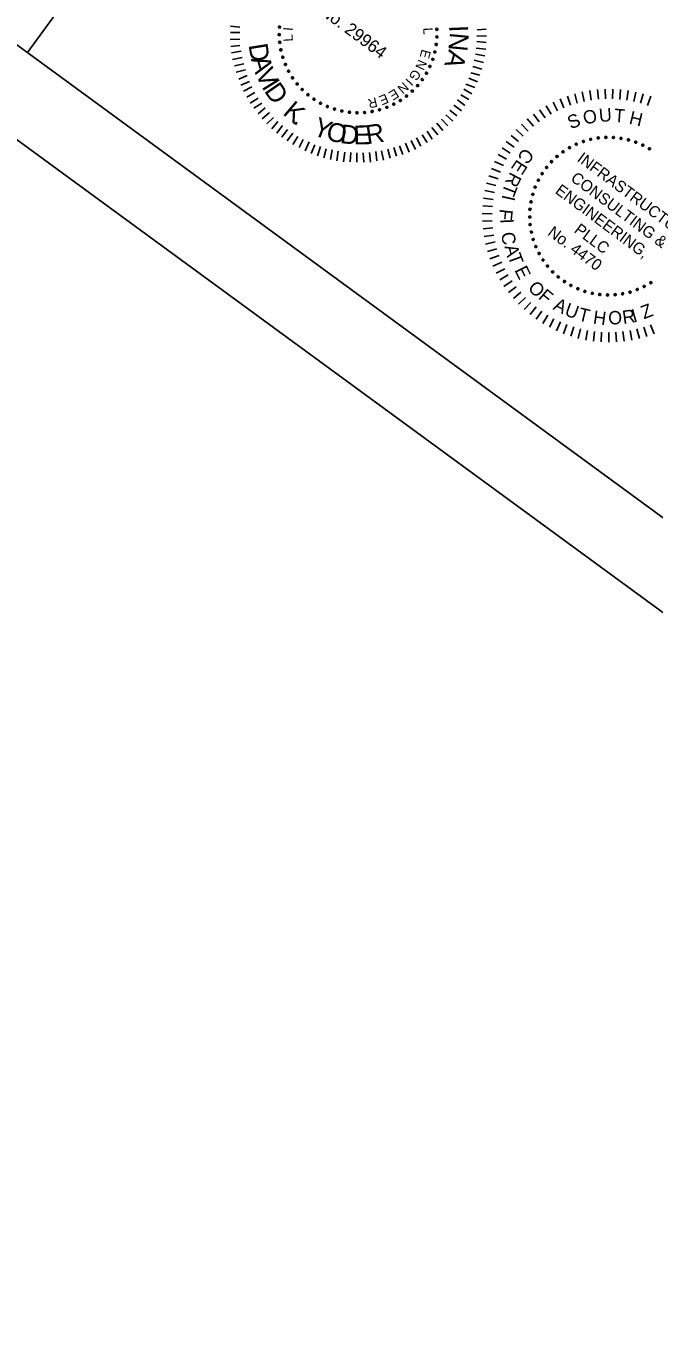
# Model space of a CAD drawing. Extents: x 1970654 to 1970899, y 796145 to 796378.
# Drawn here: x 1970805.45 to 1970821.89, y 796145.21 to 796179.11 of the extents above; entities that cross this region are included whole.
import ezdxf

# ---------------------------------------------------------------- set-up
doc = ezdxf.new("R2010")
doc.units = 0
for name, color, linetype in [('BR_BORDER LINES', 7, 'Continuous'), ('BR_TEXT', 7, 'Continuous'), ('Level 31', 7, 'Continuous')]:
    doc.layers.add(name, color=color, linetype=linetype)

msp = doc.modelspace()

# ---------------------------------------------------------------- linework, layer by layer
at = {"layer": 'BR_BORDER LINES'}
for p, q in [((1970738.359, 796227.562), (1970847.014, 796148.01)), ((1970805.492, 796178.411), (1970811.99, 796187.287))]:
    msp.add_line(p, q, dxfattribs=at)
at = {"layer": 'BR_TEXT'}
for p, q in [((1970811.052, 796179.077), (1970810.803, 796179.104)), ((1970817.254, 796179.007), (1970817.495, 796179.021)), ((1970811.054, 796178.763), (1970810.8, 796178.756)), ((1970811.051, 796178.932), (1970810.803, 796178.933)), ((1970817.251, 796178.843), (1970817.502, 796178.852)), ((1970817.253, 796178.696), (1970817.498, 796178.675)), ((1970811.054, 796178.596), (1970810.815, 796178.569)), ((1970811.086, 796178.444), (1970810.834, 796178.405)), ((1970817.212, 796178.371), (1970817.462, 796178.321)), ((1970817.236, 796178.524), (1970817.483, 796178.499)), ((1970811.107, 796178.278), (1970810.862, 796178.23)), ((1970811.151, 796178.118), (1970810.908, 796178.062)), ((1970817.144, 796178.044), (1970817.377, 796177.978)), ((1970817.181, 796178.209), (1970817.423, 796178.154)), ((1970811.197, 796177.955), (1970810.955, 796177.895)), ((1970811.244, 796177.812), (1970811.02, 796177.718)), ((1970811.304, 796177.657), (1970811.076, 796177.557)), ((1970817.039, 796177.742), (1970817.266, 796177.645)), ((1970817.092, 796177.882), (1970817.33, 796177.816)), ((1970811.367, 796177.511), (1970811.148, 796177.396)), ((1970811.444, 796177.368), (1970811.234, 796177.247)), ((1970816.907, 796177.45), (1970817.116, 796177.334)), ((1970816.966, 796177.587), (1970817.196, 796177.493)), ((1970819.809, 796177.331), (1970819.878, 796177.086)), ((1970820.005, 796177.38), (1970820.059, 796177.131)), ((1970820.204, 796177.416), (1970820.243, 796177.164)), ((1970820.404, 796177.441), (1970820.428, 796177.187)), ((1970820.606, 796177.453), (1970820.614, 796177.198)), ((1970820.808, 796177.452), (1970820.8, 796177.198)), ((1970821.009, 796177.44), (1970820.986, 796177.186)), ((1970821.21, 796177.415), (1970821.171, 796177.163)), ((1970821.408, 796177.378), (1970821.354, 796177.129)), ((1970821.604, 796177.329), (1970821.535, 796177.084)), ((1970811.527, 796177.221), (1970811.323, 796177.09)), ((1970811.625, 796177.088), (1970811.414, 796176.954)), ((1970816.652, 796177.033), (1970816.847, 796176.888)), ((1970816.742, 796177.171), (1970816.935, 796177.028)), ((1970816.831, 796177.302), (1970817.043, 796177.178)), ((1970819.066, 796177.02), (1970819.192, 796176.799)), ((1970819.244, 796177.115), (1970819.357, 796176.886)), ((1970819.428, 796177.198), (1970819.526, 796176.964)), ((1970819.617, 796177.27), (1970819.7, 796177.03)), ((1970821.797, 796177.268), (1970821.713, 796177.028)), ((1970811.712, 796176.963), (1970811.526, 796176.806)), ((1970811.828, 796176.843), (1970811.633, 796176.68)), ((1970811.928, 796176.713), (1970811.758, 796176.548)), ((1970816.323, 796176.666), (1970816.49, 796176.494)), ((1970816.443, 796176.782), (1970816.62, 796176.611)), ((1970816.541, 796176.902), (1970816.73, 796176.752)), ((1970818.569, 796176.674), (1970818.734, 796176.48)), ((1970818.728, 796176.8), (1970818.88, 796176.596)), ((1970818.893, 796176.915), (1970819.033, 796176.702)), ((1970812.044, 796176.605), (1970811.883, 796176.417)), ((1970812.165, 796176.502), (1970812.017, 796176.304)), ((1970812.293, 796176.393), (1970812.148, 796176.198)), ((1970812.434, 796176.301), (1970812.292, 796176.099)), ((1970815.952, 796176.352), (1970816.085, 796176.146)), ((1970816.073, 796176.445), (1970816.231, 796176.255)), ((1970816.201, 796176.56), (1970816.361, 796176.372)), ((1970818.277, 796176.396), (1970818.464, 796176.223)), ((1970818.419, 796176.539), (1970818.595, 796176.355)), ((1970812.57, 796176.213), (1970812.436, 796176.005)), ((1970812.704, 796176.134), (1970812.598, 796175.923)), ((1970812.86, 796176.074), (1970812.756, 796175.843)), ((1970813.008, 796175.997), (1970812.917, 796175.771)), ((1970815.223, 796175.97), (1970815.315, 796175.743)), ((1970815.382, 796176.035), (1970815.477, 796175.806)), ((1970815.528, 796176.111), (1970815.641, 796175.877)), ((1970815.672, 796176.183), (1970815.788, 796175.96)), ((1970815.816, 796176.261), (1970815.946, 796176.056)), ((1970818.021, 796176.084), (1970818.228, 796175.935)), ((1970818.144, 796176.244), (1970818.341, 796176.082)), ((1970813.156, 796175.948), (1970813.085, 796175.709)), ((1970813.311, 796175.892), (1970813.244, 796175.659)), ((1970813.468, 796175.861), (1970813.422, 796175.616)), ((1970813.624, 796175.83), (1970813.59, 796175.577)), ((1970813.793, 796175.803), (1970813.765, 796175.554)), ((1970813.953, 796175.795), (1970813.935, 796175.547)), ((1970814.112, 796175.783), (1970814.113, 796175.543)), ((1970814.278, 796175.788), (1970814.294, 796175.54)), ((1970814.441, 796175.795), (1970814.468, 796175.544)), ((1970814.604, 796175.823), (1970814.633, 796175.575)), ((1970814.756, 796175.838), (1970814.809, 796175.593)), ((1970814.924, 796175.88), (1970814.979, 796175.643)), ((1970815.081, 796175.93), (1970815.15, 796175.695)), ((1970817.805, 796175.743), (1970818.028, 796175.62)), ((1970817.908, 796175.916), (1970818.123, 796175.78)), ((1970817.632, 796175.378), (1970817.868, 796175.283)), ((1970817.713, 796175.563), (1970817.943, 796175.454)), ((1970817.504, 796174.995), (1970817.75, 796174.93)), ((1970817.562, 796175.188), (1970817.804, 796175.108)), ((1970817.424, 796174.599), (1970817.677, 796174.565)), ((1970817.458, 796174.798), (1970817.708, 796174.748)), ((1970817.403, 796174.399), (1970817.657, 796174.379)), ((1970817.393, 796174.197), (1970817.648, 796174.193)), ((1970817.396, 796173.995), (1970817.651, 796174.007)), ((1970817.411, 796173.794), (1970817.665, 796173.821)), ((1970817.439, 796173.593), (1970817.69, 796173.636)), ((1970817.478, 796173.395), (1970817.726, 796173.453)), ((1970817.53, 796173.2), (1970817.774, 796173.273)), ((1970817.593, 796173.009), (1970817.833, 796173.096)), ((1970817.668, 796172.821), (1970817.902, 796172.923)), ((1970817.755, 796172.638), (1970817.981, 796172.754)), ((1970817.852, 796172.461), (1970818.071, 796172.591)), ((1970817.96, 796172.291), (1970818.171, 796172.433)), ((1970818.078, 796172.127), (1970818.28, 796172.282)), ((1970818.206, 796171.971), (1970818.397, 796172.138)), ((1970818.343, 796171.822), (1970818.524, 796172.001)), ((1970818.489, 796171.683), (1970818.659, 796171.872)), ((1970818.643, 796171.552), (1970818.801, 796171.752)), ((1970818.804, 796171.431), (1970818.95, 796171.64)), ((1970818.973, 796171.321), (1970819.106, 796171.538)), ((1970819.149, 796171.22), (1970819.268, 796171.445)), ((1970819.33, 796171.131), (1970819.435, 796171.363)), ((1970819.516, 796171.053), (1970819.607, 796171.291)), ((1970819.707, 796170.986), (1970819.783, 796171.229)), ((1970821.695, 796170.984), (1970821.618, 796171.227)), ((1970821.886, 796171.051), (1970821.795, 796171.288)), ((1970819.901, 796170.931), (1970819.962, 796171.178)), ((1970820.098, 796170.888), (1970820.144, 796171.139)), ((1970820.298, 796170.857), (1970820.329, 796171.11)), ((1970820.499, 796170.839), (1970820.514, 796171.093)), ((1970820.701, 796170.832), (1970820.701, 796171.087)), ((1970820.902, 796170.838), (1970820.887, 796171.093)), ((1970821.104, 796170.857), (1970821.072, 796171.109)), ((1970821.303, 796170.887), (1970821.257, 796171.138)), ((1970821.501, 796170.93), (1970821.439, 796171.177))]:
    msp.add_line(p, q, dxfattribs=at)
for centre, start, end in [((1970812.088, 796179.076), 85.1636, 265.1636), ((1970812.088, 796179.076), 265.1636, 85.1636), ((1970816.202, 796179.019), 93.4713, 273.4713), ((1970816.202, 796179.019), 273.4713, 93.4713), ((1970812.08, 796178.877), 90.702, 270.702), ((1970812.092, 796178.678), 96.2405, 276.2405), ((1970812.08, 796178.877), 270.702, 90.702), ((1970812.092, 796178.678), 276.2405, 96.2405), ((1970816.204, 796178.82), 87.9328, 267.9328), ((1970816.204, 796178.82), 267.9328, 87.9328), ((1970812.123, 796178.481), 101.779, 281.779), ((1970812.123, 796178.481), 281.779, 101.779), ((1970816.151, 796178.425), 76.8559, 256.8559), ((1970816.151, 796178.425), 256.8559, 76.8559), ((1970816.187, 796178.621), 82.3943, 262.3943), ((1970816.187, 796178.621), 262.3943, 82.3943), ((1970812.173, 796178.288), 107.3174, 287.3174), ((1970812.173, 796178.288), 287.3174, 107.3174), ((1970812.241, 796178.101), 112.8559, 292.8559), ((1970812.241, 796178.101), 292.8559, 112.8559), ((1970816.023, 796178.048), 65.779, 245.779), ((1970816.023, 796178.048), 245.779, 65.779), ((1970816.096, 796178.233), 71.3174, 251.3174), ((1970816.096, 796178.233), 251.3174, 71.3174), ((1970812.327, 796177.921), 118.3943, 298.3943), ((1970812.327, 796177.921), 298.3943, 118.3943), ((1970812.429, 796177.75), 123.9328, 303.9328), ((1970812.429, 796177.75), 303.9328, 123.9328), ((1970815.824, 796177.703), 54.702, 234.702), ((1970815.824, 796177.703), 234.702, 54.702), ((1970815.932, 796177.871), 60.2405, 240.2405), ((1970815.932, 796177.871), 240.2405, 60.2405), ((1970812.548, 796177.59), 129.4713, 309.4713), ((1970812.548, 796177.59), 309.4713, 129.4713), ((1970812.682, 796177.442), 135.0097, 315.0097), ((1970812.682, 796177.442), 315.0097, 135.0097), ((1970812.829, 796177.308), 140.5482, 320.5482), ((1970812.829, 796177.308), 320.5482, 140.5482), ((1970815.563, 796177.402), 43.6251, 223.6251), ((1970815.563, 796177.402), 223.6251, 43.6251), ((1970815.701, 796177.546), 49.1636, 229.1636), ((1970815.701, 796177.546), 229.1636, 49.1636), ((1970812.989, 796177.188), 146.0866, 326.0866), ((1970812.989, 796177.188), 326.0866, 146.0866), ((1970813.159, 796177.085), 151.6251, 331.6251), ((1970813.159, 796177.085), 331.6251, 151.6251), ((1970813.339, 796176.999), 157.1636, 337.1636), ((1970813.339, 796176.999), 337.1636, 157.1636), ((1970814.894, 796176.977), 21.4713, 201.4713), ((1970814.894, 796176.977), 201.4713, 21.4713), ((1970815.076, 796177.058), 27.0097, 207.0097), ((1970815.076, 796177.058), 207.0097, 27.0097), ((1970815.25, 796177.157), 32.5482, 212.5482), ((1970815.25, 796177.157), 212.5482, 32.5482), ((1970815.412, 796177.272), 38.0866, 218.0866), ((1970815.412, 796177.272), 218.0866, 38.0866), ((1970813.526, 796176.93), 162.702, 342.702), ((1970813.526, 796176.93), 342.702, 162.702), ((1970813.719, 796176.879), 348.2405, 168.2405), ((1970813.719, 796176.879), 168.2405, 348.2405), ((1970813.916, 796176.848), 353.779, 173.779), ((1970813.916, 796176.848), 173.779, 353.779), ((1970814.114, 796176.835), 359.3174, 179.3174), ((1970814.114, 796176.835), 179.3174, 359.3174), ((1970814.314, 796176.842), 4.8559, 184.8559), ((1970814.314, 796176.842), 184.8559, 4.8559), ((1970814.511, 796176.868), 10.3943, 190.3943), ((1970814.511, 796176.868), 190.3943, 10.3943), ((1970814.705, 796176.913), 15.9328, 195.9328), ((1970814.705, 796176.913), 195.9328, 15.9328), ((1970819.851, 796176.012), 24.2405, 204.2405), ((1970819.851, 796176.012), 204.2405, 24.2405), ((1970820.037, 796176.085), 18.702, 198.702), ((1970820.037, 796176.085), 198.702, 18.702), ((1970820.229, 796176.139), 13.1636, 193.1636), ((1970820.229, 796176.139), 193.1636, 13.1636), ((1970820.425, 796176.175), 7.6251, 187.6251), ((1970820.425, 796176.175), 187.6251, 7.6251), ((1970820.623, 796176.191), 2.0866, 182.0866), ((1970820.623, 796176.191), 182.0866, 2.0866), ((1970820.823, 796176.188), 356.5482, 176.5482), ((1970820.823, 796176.188), 176.5482, 356.5482), ((1970821.021, 796176.166), 351.0097, 171.0097), ((1970821.021, 796176.166), 171.0097, 351.0097), ((1970821.216, 796176.125), 165.4713, 345.4713), ((1970821.216, 796176.125), 345.4713, 165.4713), ((1970821.406, 796176.066), 159.9328, 339.9328), ((1970821.406, 796176.066), 339.9328, 159.9328), ((1970821.589, 796175.988), 154.3943, 334.3943), ((1970821.589, 796175.988), 334.3943, 154.3943), ((1970819.348, 796175.692), 40.8559, 220.8559), ((1970819.348, 796175.692), 220.8559, 40.8559), ((1970819.505, 796175.815), 35.3174, 215.3174), ((1970819.505, 796175.815), 215.3174, 35.3174), ((1970819.673, 796175.922), 29.779, 209.779), ((1970819.673, 796175.922), 209.779, 29.779), ((1970821.765, 796175.893), 148.8559, 328.8559), ((1970821.765, 796175.893), 328.8559, 148.8559), ((1970819.073, 796175.405), 51.9328, 231.9328), ((1970819.073, 796175.405), 231.9328, 51.9328), ((1970819.203, 796175.555), 46.3943, 226.3943), ((1970819.203, 796175.555), 226.3943, 46.3943), ((1970818.858, 796175.069), 63.0097, 243.0097), ((1970818.858, 796175.069), 243.0097, 63.0097), ((1970818.957, 796175.242), 57.4713, 237.4713), ((1970818.957, 796175.242), 237.4713, 57.4713), ((1970818.712, 796174.699), 74.0866, 254.0866), ((1970818.712, 796174.699), 254.0866, 74.0866), ((1970818.776, 796174.888), 68.5482, 248.5482), ((1970818.776, 796174.888), 248.5482, 68.5482), ((1970818.639, 796174.308), 85.1636, 265.1636), ((1970818.639, 796174.308), 265.1636, 85.1636), ((1970818.666, 796174.505), 79.6251, 259.6251), ((1970818.666, 796174.505), 259.6251, 79.6251), ((1970818.632, 796174.108), 90.702, 270.702), ((1970818.643, 796173.909), 96.2405, 276.2405), ((1970818.632, 796174.108), 270.702, 90.702), ((1970818.643, 796173.909), 276.2405, 96.2405), ((1970818.674, 796173.712), 101.779, 281.779), ((1970818.674, 796173.712), 281.779, 101.779), ((1970818.724, 796173.519), 107.3174, 287.3174), ((1970818.724, 796173.519), 287.3174, 107.3174), ((1970818.792, 796173.332), 112.8559, 292.8559), ((1970818.792, 796173.332), 292.8559, 112.8559), ((1970818.878, 796173.152), 118.3943, 298.3943), ((1970818.878, 796173.152), 298.3943, 118.3943), ((1970818.981, 796172.981), 123.9328, 303.9328), ((1970818.981, 796172.981), 303.9328, 123.9328), ((1970819.099, 796172.821), 129.4713, 309.4713), ((1970819.099, 796172.821), 309.4713, 129.4713), ((1970819.233, 796172.674), 135.0097, 315.0097), ((1970819.233, 796172.674), 315.0097, 135.0097), ((1970819.38, 796172.539), 320.5482, 140.5482), ((1970819.38, 796172.539), 140.5482, 320.5482), ((1970819.54, 796172.42), 146.0866, 326.0866), ((1970819.54, 796172.42), 326.0866, 146.0866), ((1970819.71, 796172.316), 151.6251, 331.6251), ((1970819.71, 796172.316), 331.6251, 151.6251), ((1970819.89, 796172.23), 157.1636, 337.1636), ((1970819.89, 796172.23), 337.1636, 157.1636), ((1970821.446, 796172.208), 21.4713, 201.4713), ((1970821.627, 796172.29), 27.0097, 207.0097), ((1970821.627, 796172.29), 207.0097, 27.0097), ((1970821.801, 796172.388), 32.5482, 212.5482), ((1970821.801, 796172.388), 212.5482, 32.5482), ((1970820.077, 796172.161), 162.702, 342.702), ((1970820.077, 796172.161), 342.702, 162.702), ((1970820.27, 796172.111), 348.2405, 168.2405), ((1970820.27, 796172.111), 168.2405, 348.2405), ((1970820.467, 796172.079), 353.779, 173.779), ((1970820.467, 796172.079), 173.779, 353.779), ((1970820.666, 796172.067), 359.3174, 179.3174), ((1970820.666, 796172.067), 179.3174, 359.3174), ((1970820.865, 796172.074), 4.8559, 184.8559), ((1970820.865, 796172.074), 184.8559, 4.8559), ((1970821.062, 796172.1), 10.3943, 190.3943), ((1970821.062, 796172.1), 190.3943, 10.3943), ((1970821.257, 796172.145), 15.9328, 195.9328), ((1970821.257, 796172.145), 195.9328, 15.9328), ((1970821.446, 796172.208), 201.4713, 21.4713)]:
    msp.add_arc(centre, 0.028, start, end, dxfattribs=at)
at = {"layer": 'Level 31'}
msp.add_lwpolyline([(1970731.261, 796230.28), (1970847.449, 796145.214), (1970899.434, 796216.218), (1970783.245, 796301.284)], close=True, dxfattribs=at)

# ---------------------------------------------------------------- texts
at = {"layer": 'BR_TEXT'}
for s, height, rotation, p in [('No. 29964', 0.327, 323.3174, (1970813.121, 796179.439)), ('I', 0.249, 84.8917, (1970812.431, 796178.97)), ('L', 0.249, 273.2452, (1970815.846, 796179.057)), ('I', 0.496, 272.4519, (1970816.522, 796179.116)), ('L', 0.249, 93.7501, (1970812.439, 796178.706)), ('N', 0.496, 264.4942, (1970816.551, 796178.949)), ('D', 0.494, 279.1958, (1970811.277, 796178.611)), ('E', 0.249, 254.8396, (1970815.812, 796178.511)), ('A', 0.496, 253.2698, (1970816.523, 796178.509)), ('A', 0.494, 286.6283, (1970811.337, 796178.242)), ('V', 0.494, 294.3085, (1970811.448, 796177.872)), ('N', 0.249, 245.6372, (1970815.73, 796178.248)), ('I', 0.494, 301.9887, (1970811.608, 796177.52)), ('I', 0.249, 226.1989, (1970815.426, 796177.756)), ('G', 0.249, 236.09, (1970815.602, 796177.994)), ('D', 0.494, 304.5901, (1970811.673, 796177.406)), ('E', 0.249, 202.775, (1970814.87, 796177.339)), ('E', 0.249, 211.9773, (1970815.109, 796177.475)), ('N', 0.249, 221.5245, (1970815.33, 796177.655)), ('K', 0.494, 319.8885, (1970812.151, 796176.805)), ('R', 0.249, 193.5726, (1970814.613, 796177.242)), ('Y', 0.494, 338.6555, (1970812.927, 796176.273)), ('S', 0.349, 22.6989, (1970819.709, 796176.397)), ('O', 0.349, 13.6688, (1970820.073, 796176.518)), ('U', 0.349, 4.6388, (1970820.457, 796176.589)), ('T', 0.349, 355.6088, (1970820.826, 796176.597)), ('H', 0.349, 346.5788, (1970821.212, 796176.55)), ('.', 0.494, 326.9494, (1970812.422, 796176.576)), ('O', 0.494, 346.2118, (1970813.281, 796176.135)), ('D', 0.494, 353.892, (1970813.657, 796176.044)), ('E', 0.494, 1.3245, (1970814.029, 796176.004)), ('R', 0.494, 8.3853, (1970814.384, 796176.011)), ('C', 0.349, 230.8156, (1970818.506, 796175.939)), ('INFRASTRUCTURE', 0.29909, 323.3174, (1970819.852, 796175.586)), ('E', 0.349, 236.8156, (1970818.304, 796175.633)), ('R', 0.349, 242.8156, (1970818.127, 796175.305)), ('ENGINEERING,', 0.29909, 323.3174, (1970819.277, 796174.748)), ('CONSULTING &', 0.29909, 323.3174, (1970819.681, 796175.073)), ('I', 0.349, 257.5619, (1970817.921, 796174.704)), ('T', 0.349, 248.8156, (1970817.997, 796175.01)), ('F', 0.349, 263.5619, (1970817.85, 796174.329)), ('I', 0.349, 272.3174, (1970817.859, 796174.055)), ('PLLC', 0.2991, 323.3174, (1970819.773, 796173.722)), ('C', 0.349, 278.3174, (1970817.885, 796173.689)), ('No. 4470', 0.2991, 323.3174, (1970819.079, 796173.651)), ('A', 0.349, 284.3174, (1970817.969, 796173.336)), ('T', 0.349, 290.3174, (1970818.054, 796173.084)), ('E', 0.349, 296.3174, (1970818.227, 796172.72)), ('O', 0.349, 314.3174, (1970818.564, 796172.231)), ('F', 0.349, 320.3174, (1970818.838, 796171.986)), ('A', 0.349, 334.3174, (1970819.221, 796171.697)), ('U', 0.349, 340.3174, (1970819.523, 796171.542)), ('T', 0.349, 346.3174, (1970819.877, 796171.404)), ('H', 0.349, 352.3174, (1970820.276, 796171.319)), ('O', 0.349, 2.3174, (1970820.693, 796171.291)), ('R', 0.349, 8.3174, (1970821.082, 796171.304)), ('I', 0.349, 16.1245, (1970821.353, 796171.34)), ('Z', 0.349, 21.186, (1970821.622, 796171.429))]:
    msp.add_text(s, height=height, rotation=rotation, dxfattribs=at).set_placement(p)

doc.saveas('drawing.dxf')
